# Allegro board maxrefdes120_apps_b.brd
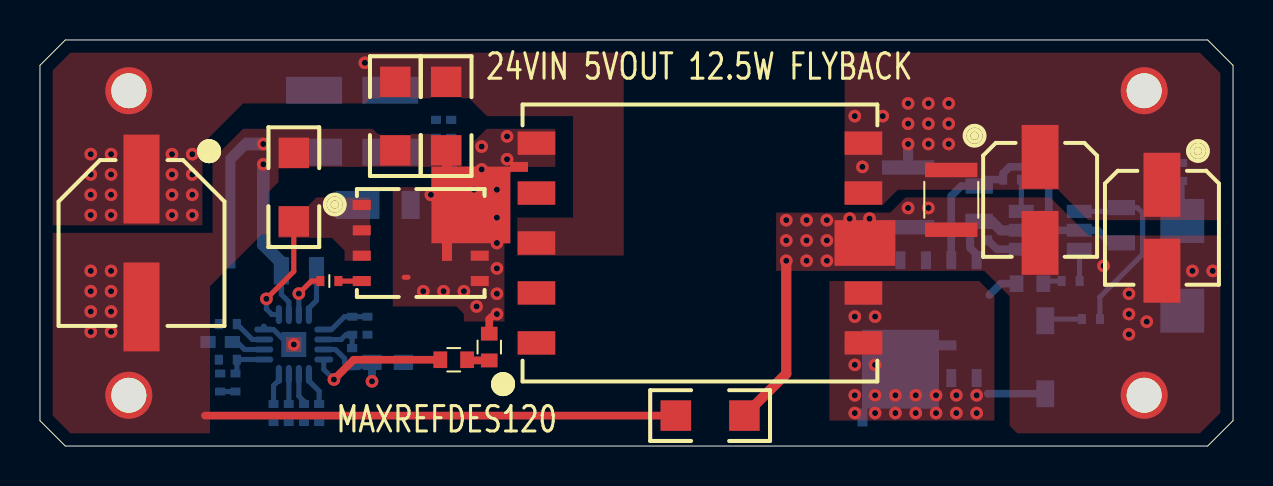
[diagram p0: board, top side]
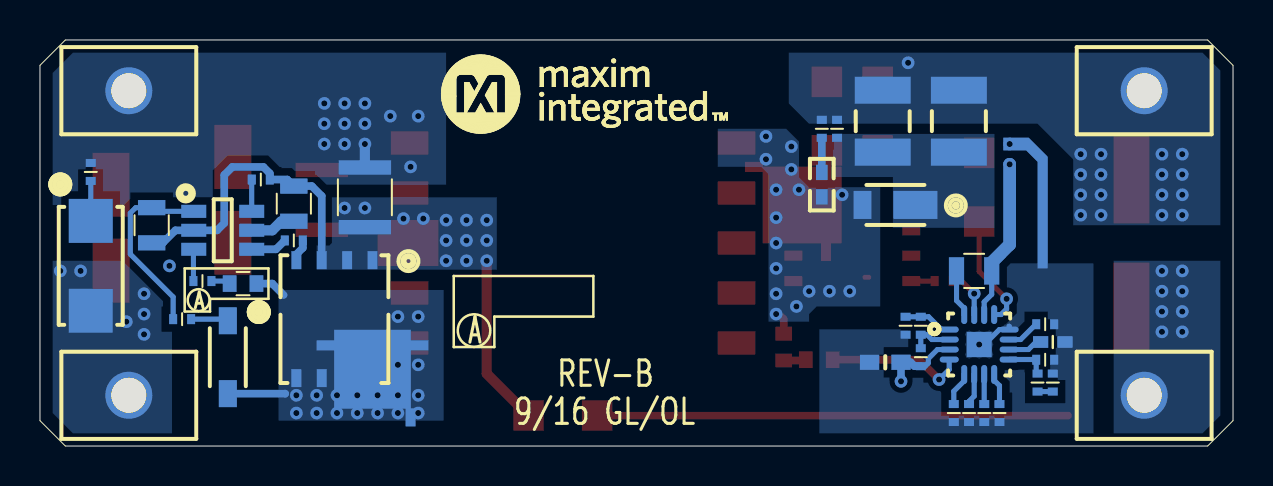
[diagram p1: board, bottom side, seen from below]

Outline 59.69 x 20.32 mm; copper layers: TOP, LAYER2, LAYER3, BOTTOM. Coordinates in mm from the lower left corner of the outline.
Outline path: 0,19.05 1.27,20.32 58.42,20.32 59.69,19.05 59.69,1.27 58.42,0 1.27,0 0,1.27 0,19.05

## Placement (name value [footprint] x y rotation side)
C1  10UF  [1206]  17.78 16.51 270 top
C2  10UF  [1206]  20.32 16.51 270 top
C3  0.047UF  [0402]  19.81 15.88 270 bottom
C4  OPEN  [0402#2]  20.57 13.08 270 bottom
C5  1UF  [0603#2]  17.4 4.19 0 bottom
C6  2.2UF  [0805]  12.95 8.76 0 bottom
C7  4700PF  [0402#2]  9.02 5.21 180 bottom
C8  330PF  [0402]  9.4 4.32 180 bottom
C9  0.033UF  [0402]  9.02 3.17 90 bottom
C10  1000PF  [1206]  33.53 1.52 0 top
C12  2.2UF  [0805]  54.1 11.05 270 bottom
C13  2.2UF  [0805]  46.99 12.13 90 bottom
C15  100UF  [1210]  43.43 12.45 270 bottom
C16  220UF  [CAPAE530X600M]  50.04 12.32 270 top
C17  220UF  [CAPAE530X600M]  56.13 10.92 270 top
C18  47UF  [CAPAE830X690M]  5.08 10.16 270 top
C19  100UF  [1210]  45.59 12.32 270 top
D1  DFLS2100  [POWERI123]  16.89 12.06 0 bottom
D2  1N4148W-7-F  [SOD3718X135M]  50.29 4.45 270 bottom
D3  5.6V  [DIOM5528X230M]  57.15 9.02 270 bottom
EV_KIT_BOX1  SMALL BOX  [EVKIT_PACKAGING]  83.82 40.64 0 top
GND  FWJ-01-01-T-S  [SAMTEC_FWJ-01-01-X-X]  4.45 2.54 90 bottom
GNDO  FWJ-01-01-T-S  [SAMTEC_FWJ-01-01-X-X]  55.24 2.54 90 bottom
N1  FDMS86102LZ  [SON127P615X500X112-8M_POWERPAK_SINGLE]  19.05 10.16 0 top
N2  BSC059N04LSG  [SON127P615X500X112-8M_POWERPAK_SINGLE]  44.96 6.35 270 bottom
NOREF  -  []  59 0.58 0 top
NOREF#2  -  []  12.7 -8.26 0 top
NOREF#3  -  []  30.48 55.88 0 top
NOREF#4  -  []  0 19.05 0 top
NOREF#5  -  []  55.24 2.54 90 top
NOREF#6  -  []  1.27 0 90 top
NOREF#7  -  []  4.45 17.78 0 top
NOREF#8  -  []  37.59 17.53 180 bottom
PTC1  470  [0603]  49.53 8.13 0 bottom
R1  7.5K  [RESC3225X65M]  17.53 16.26 270 bottom
R2  274K  [0402]  15.62 4.45 270 bottom
R3  11.3K  [0402]  15.62 6.02 270 bottom
R4  9.76K  [0402]  16.38 6.02 90 bottom
R5  10K  [0402]  13.97 1.65 270 bottom
R6  OPEN  [0402]  13.21 1.65 270 bottom
R7  49.9K  [0402]  9.4 6.1 180 bottom
R8  75K  [0402]  12.45 1.65 270 bottom
R9  90.9K  [0402]  11.68 1.65 270 bottom
R10  10.5K  [0402]  9.78 3.17 270 bottom
R11  0.012  [1206]  12.7 12.95 90 top
R12  150K  [0603]  20.7 4.32 180 top
R13  OPEN  [0402]  20.57 15.88 270 bottom
R15  10  [0402]  52.58 6.35 180 bottom
R16  1K  [0402]  51.56 8.26 180 bottom
R17  54.9K  [0402]  48.64 13.34 180 bottom
R18  1K  [0603]  22.48 4.95 270 top
R19  10  [0402]  14.48 8.26 0 top
R20  7.5K  [RESC3225X65M]  13.72 16.26 270 bottom
R21  0  [0402]  57.15 13.72 270 bottom
R22  5.1  [0402]  46.99 10.29 180 bottom
T1  750343289  [WURT_750343289]  33.02 10.16 0 top
U1  MAX17690ATE+  [QFN50P300X300X80-17M]  12.7 5.08 180 bottom
U2  MAX17606AZT+  [SOT95P280X110-6M]  50.55 10.79 180 bottom
VIN  FWJ-01-01-T-S  [SAMTEC_FWJ-01-01-X-X]  4.45 17.78 90 bottom
VOUT  FWJ-01-01-T-S  [SAMTEC_FWJ-01-01-X-X]  55.24 17.78 90 bottom
X1  -  [EVKIT_WIRE]  79.38 33.02 0 top

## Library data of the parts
C1 C2 = CAP_NP: alternate symbols: CAPC3216X90L; part number: CAP_NP_1206CAP-1206,10UF,20-0010U-Y6
C3 = CAP_NP: alternate symbols: 0402_NOSILK,CAPC1005X50L; part number: CAP_NP_0402CAP-0402,0.047UF,20-0U047-04C
C4 = EVK_GENERIC_CAPACITORS: alternate symbols: 0402_NOSILK,CAPC1005X50L; part number: EVK_GENERIC_CAPACITORS_0402CAP-0402,N/A
C5 = CAP_NP: alternate symbols: (0603_NOSILK); part number: CAP_NP_0603CAP-0603,1UF,20-0001U-14
C6 C12 C13 = CAP_NP: alternate symbols: CAPC2012X145L,CAPC2012X140M; part number: CAP_NP_0805CAP-0805,2.2UF,20-002U2-04
C7 = CAP_NP: alternate symbols: 0402_NOSILK,CAPC1005X50L; part number: CAP_NP_0402CAP-0402,4700PF,20-4700P-14
C8 = CAP_NP: alternate symbols: 0402_NOSILK,CAPC1005X50L; part number: CAP_NP_0402CAP-0402,330PF,20-0330P-14
C9 = CAP_NP: alternate symbols: 0402_NOSILK,CAPC1005X50L; part number: CAP_NP_0402CAP-0402,0.033UF,20-0U033-04C
C10 = CAP_NP: part number: CAP_NP_1206CAP-1206,1000PF,20-1000P-08B
C15 C19 = CAP_NP: alternate symbols: CAPC3225X270L; part number: CAP_NP_1210CAP-1210,100UF,20-0100U-V5A
C16 C17 = CAP_POL: part number: CAP_POL_CASE_B6-CAPAE530X600M,220UF,20-0220U-CA36
C18 = CAP_POL: part number: CAP_POL_CASEE-CAPAE830X690M,47UF,20-0047U-A49
D1 = DIO_SCHOTTKY: alternate symbols: SODFL3717X100L; part number: DIO_SCHOTTKY_POWERI123-POWERI123,DFLS2100,30-DFLS2100-00
D2 = DIO_SWITCH: part number: DIO_SWITCH_SOD-123-SOD3718X135M,1N4148W-7-F,30-1N4148W7F-00
D3 = DIO_ZENER: part number: DIO_ZENER_DO-214AC-DIOM5528X230M,5.6V,30-SMAZ5V6-00
EV_KIT_BOX1 = EV_KIT_BOX: part number: EV_KIT_BOX_ACCESSORY-N/A,SMALL BOX,EVKIT_PACKAGING
GND GNDO VIN VOUT = HEADER_1P: part number: HEADER_1P_TH-SAMTEC_FWJ-01-01-X-X,FWJ-01-01-T-S,01-FWJ0101TS1P-19
N1 = TRAN_NCH_8P: part number: TRAN_NCH_8P_PG-TSDSON-8-SON127P615X500X112-8M_POWERPAK_SINGLE,FDMS86102LZ,90-FDMS86102LZ-23
N2 = TRAN_NCH_8P: part number: TRAN_NCH_8P_PG-TDSON-8-SON127P615X500X112-8M_POWERPAK_SINGLE,BSC059N04LSG,90-BSC059N04LSG-23
PTC1 = THERMISTOR_SMD: alternate symbols: RESC1608X90L; part number: THERMISTOR_SMD_0603-0603,470,83-0470R-0AD
R1 R20 = RES: alternate symbols: RESC3225X70L; part number: RES_1210RES-RESC3225X65M,7.5K,80-007K5-BA51
R2 = RES: alternate symbols: (0402_NOSILK,RESC1005X50L); part number: RES_0402RES-0402,274K,80-0274K-23
R3 = RES: alternate symbols: 0402_NOSILK,RESC1005X50L; part number: RES_0402RES-0402,11.3K,80-011K3-AA23
R4 = RES: alternate symbols: 0402_NOSILK,RESC1005X50L; part number: RES_0402RES-0402,9.76K,80-09K76-AA23
R5 = RES: alternate symbols: 0402_NOSILK,RESC1005X50L; part number: RES_0402RES-0402,10K,80-0010K-23
R6 R13 = EVK_GENERIC_RESISTORS: alternate symbols: 0402_NOSILK,RESC1005X50L; part number: EVK_GENERIC_RESISTORS_0402RES-0402,N/A
R7 = RES: alternate symbols: (0402_NOSILK,RESC1005X50L); part number: RES_0402RES-0402,49.9K,80-049K9-18
R8 = RES: alternate symbols: (0402_NOSILK,RESC1005X50L); part number: RES_0402RES-0402,75K,80-0075K-23
R9 = RES: alternate symbols: (0402_NOSILK,RESC1005X50L); part number: RES_0402RES-0402,90.9K,80-090K9-23
R10 = RES: alternate symbols: (0402_NOSILK,RESC1005X50L); part number: RES_0402RES-0402,10.5K,80-010K5-18A
R11 = RES: alternate symbols: RESC3116X60L; part number: RES_1206RES-1206,0.012,80-0R012-BA25
R12 = RES: alternate symbols: 0603_NOSILK,RESC1608X90L; part number: RES_0603RES-0603,150K,80-0150K-24
R15 R19 = RES: alternate symbols: (0402_NOSILK,RESC1005X50L); part number: RES_0402RES-0402,10,80-0010R-49
R16 = RES: alternate symbols: 0402_NOSILK,RESC1005X50L,RES0402-NOT_FOR_TEST; part number: RES_0402RES-0402,1K,80-0001K-23
R17 = RES: alternate symbols: (0402_NOSILK,RESC1005X50L); part number: RES_0402RES-0402,54.9K,80-054K9-23
R18 = RES: alternate symbols: 0603_NOSILK,RESC1608X90L; part number: RES_0603RES-0603,1K,80-0001K-24
R21 = RES: alternate symbols: (0402_NOSILK,RESC1005X50L); part number: RES_0402RES-0402,0,80-0000R-26B
R22 = RES: alternate symbols: (0402_NOSILK,RESC1005X50L); part number: RES_0402RES-0402,5.1,80-005R1-U21
T1 = EK_750343289: part number: EK_750343289_SMD-WURT_750343289,750343289,N/A
U1 = MAX17690: part number: MAX17690_TQFN16-EP-QFN50P300X300X80-17M,MAX17690ATE+,10-MAX17690ATE-T
U2 = MAX17606: part number: MAX17606_SOT23-6-SOT95P280X110-6M,MAX17606AZT+,10-MAX17606AZT-Z
X1 = EVKIT_WIRE: part number: EVKIT_WIRE_WIRE-EVKIT_WIRE,N/A,EVKIT_WIRE

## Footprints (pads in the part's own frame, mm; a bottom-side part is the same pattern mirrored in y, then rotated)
0402
  rect 0.4x0.5 smd: 1(-0.45,0) 2(0.45,0)
0402#2
  rect 0.762x0.584 smd: 1(-0.61,0) 2(0.61,0)
0603
  rect 0.69x0.83 smd: 1(-0.67,0) 2(0.67,0)
0603#2
  rect 0.965x0.762 smd: 1(-0.787,0) 2(0.787,0)
0805
  rect 0.76x1.37 smd: 1(-0.88,0) 2(0.88,0)
1206
  rect 1.524x1.524 smd: 1(-1.714,0) 2(1.714,0)
1210
  rect 0.72x2.62 smd: 1(-1.495,0) 2(1.495,0)
CAPAE530X600M
  rect 3.2x1.85 smd: A(-2.15,0) K(2.15,0)
CAPAE830X690M
  rect 4.45x1.8 smd: 1(-3.2,0) 2(3.2,0)
DIOM5528X230M
  rect 2.2x2.2 smd: A(2.25,0) C(-2.25,0)
POWERI123
  rect 0.9x1.4 smd: A(1.65,0)
  rect 2.2x1.4 smd: C(-0.999,0)
QFN50P300X300X80-17M
  oval 0.95x0.3 smd: 1(-1.5,0.75) 2(-1.5,0.25) 3(-1.5,-0.25) 4(-1.5,-0.75) 9(1.5,-0.75) 10(1.5,-0.25) 11(1.5,0.25) 12(1.5,0.75)
  oval 0.3x0.95 smd: 5(-0.75,-1.5) 6(-0.25,-1.5) 7(0.25,-1.5) 8(0.75,-1.5) 13(0.75,1.5) 14(0.25,1.5) 15(-0.25,1.5) 16(-0.75,1.5)
  rect 1.25x1.25 smd: 17(0,0)
RESC3225X65M
  rect 1.35x2.8 smd: 1(-1.55,0) 2(1.55,0)
SAMTEC_FWJ-01-01-X-X
  round 2.35 hole 1.75: 1(0,0)
SOD3718X135M
  rect 1.35x0.9 smd: A(1.825,0) C(-1.825,0)
SON127P615X500X112-8M_POWERPAK_SINGLE
  rect 0.9x0.5 smd: 1(-2.95,1.905) 2(-2.95,0.635) 3(-2.95,-0.635) 4(-2.95,-1.905) 5(2.95,-1.905) 6(2.95,-0.635) 7(2.95,0.635)
  custom 1.209x1.209 smd: 8(2.95,1.905)
SOT95P280X110-6M
  rect 1.25x0.65 smd: 1(-1.45,0.95) 2(-1.45,0) 3(-1.45,-0.95) 4(1.45,-0.95) 5(1.45,0) 6(1.45,0.95)
WURT_750343289
  rect 1.88x1.17 smd: 1(-8.18,-5) 2(-8.18,-2.5) 3(-8.18,0) 4(-8.18,2.5) 5(-8.18,5) 6(8.18,5) 7(8.18,2.5) 8(8.18,0) 9(8.18,-2.5) 10(8.18,-5)

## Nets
GNDO: C10.2 C12.2 C13.2 C15.2 C16.K(B) C17.K(B) C19.2 D3.A GNDO.1 N2.1(S1) N2.2(S2) N2.3(S3) R17.2 U2.2(GND)
PGND: C1.2 C2.2 C6.1 C10.1 C18.2(B) GND.1 R11.2 U1.14(PGND)
SGND: C5.2 C7.2 C8.2 C9.2 R4.1 R5.2 R6.2 R7.2 R8.2 R9.2 U1.12(SGND) U1.17(EP)
VIN: C1.1 C2.1 C3.1 C5.1 C18.1(A) R1.1 R2.2 R13.1 R20.1 T1.3 U1.3(VIN) VIN.1
LX: C4.2 D1.A N1.5(D1) N1.6(D2) N1.7(D3) N1.8(D4) R18.1 T1.5
UNNAMED_4_CAPNP_I112_2: C3.2 D1.C(K) R1.2 R20.2
UNNAMED_4_CAPNP_I179_2: C6.2 U1.16(INTVCC)
UNNAMED_4_CAPNP_I180_1: C13.1 U2.5(VDRV)
UNNAMED_4_CAPNP_I182_1: C8.1 R10.1 U1.9(COMP)
UNNAMED_4_CAPNP_I183_1: C9.1 R10.2
UNNAMED_4_CAPNP_I184_1: C12.1 R15.1 U2.1(VIN)
UNNAMED_4_CAPNP_I216_1: C7.1 U1.10(SS)
UNNAMED_4_DIOSWITCH_I187_A: D2.A N2.5(D1) N2.6(D2) N2.7(D3) N2.8(D4) PTC1.1 T1.9 T1.10
UNNAMED_4_DIOSWITCH_I187_K: D2.C(K) R15.2
UNNAMED_4_DIOZENER_I178_K: D3.C(K) R21.2
UNNAMED_4_EVKGENERICCAPACITORS_I151_1: C4.1 R13.2
UNNAMED_4_EVKGENERICRESISTORS_I167_1: R6.1 U1.6(TC)
UNNAMED_4_MAX17606_I176_DRN: R16.1 U2.3(DRN)
UNNAMED_4_MAX17606_I176_GATE: R22.1 U2.4(GATE)
UNNAMED_4_MAX17606_I176_TOFF: R17.1 U2.6(TOFF)
UNNAMED_4_MAX17690_I155_CS: N1.1(S1) N1.2(S2) N1.3(S3) R11.1 U1.13(CS)
UNNAMED_4_MAX17690_I155_EN: R2.1 R3.2 U1.2(EN/UVLO)
UNNAMED_4_MAX17690_I155_FB: R12.2 U1.4(FB)
UNNAMED_4_MAX17690_I155_NDRV: R19.1 U1.15(NDRV)
UNNAMED_4_MAX17690_I155_OVI: R3.1 R4.2 U1.1(OVI)
UNNAMED_4_MAX17690_I155_RIN: R9.1 U1.8(RIN)
UNNAMED_4_MAX17690_I155_RT: R7.1 U1.11(RT)
UNNAMED_4_MAX17690_I155_SET: R5.1 U1.5(SET)
UNNAMED_4_MAX17690_I155_VCM: R8.1 U1.7(VCM)
UNNAMED_4_RESSMD_I171_1: R12.1 R18.2
UNNAMED_4_RESSMD_I173_2: PTC1.2 R16.2
UNNAMED_4_RESSMD_I175_2: N1.4(G) R19.2
UNNAMED_4_RESSMD_I224_2: N2.4(G) R22.2
VOUT: C15.1 C16.A C17.A C19.1 R21.1 T1.6 T1.7 VOUT.1

Pads without a net: T1 1 2 4 8

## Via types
v1: diameter 0.635, hole 0.305, TOP to BOTTOM, 98 vias

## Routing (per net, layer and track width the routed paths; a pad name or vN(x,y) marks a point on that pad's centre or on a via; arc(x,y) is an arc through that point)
GNDO: length 23.6
  TOP w0.508: v1(37.34,9.27) 37.34,3.62 C10.2
  BOTTOM w0.381: 45.59,9.81 45.59,12.51 46.09,13.01 C13.2 47.32,13.34 R17.2 48.19,13.64 48.51,13.97 50.07,13.97 50.47,13.56 50.47,11.15 50.83,10.79 U2.2 52.91,10.79 53.54,10.17 C12.2
  vias: v1(37.34,11.3) v1(37.34,10.29) v1(38.35,11.3) v1(38.35,10.29) v1(38.35,9.27) v1(39.37,11.3) v1(39.37,10.29) v1(39.37,9.27) v1(40.51,11.38) v1(41.5,11.38) v1(43.43,11.91) v1(44.45,11.91) v1(53.21,9.02) v1(54.48,7.62) v1(54.48,6.6) v1(54.48,5.59) v1(55.37,6.22) v1(57.66,8.76) v1(58.67,8.76)
PGND: length 31.6
  TOP w0.381: C10.1 8.26,1.52
  BOTTOM w0.254: C6.1 12.07,7.59 12.45,7.21 U1.14
  BOTTOM w0.635: v1(11.18,14.1) 11.18,10.08 12.07,9.18 C6.1
  vias: v1(2.54,8.76) v1(2.54,7.75) v1(2.54,6.73) v1(2.54,5.71) v1(3.56,8.76) v1(3.56,7.75) v1(3.56,6.73) v1(3.56,5.71) v1(11.18,15.11)
SGND: length 2
  BOTTOM w0.254: 11.2,5.99 11.2,5.99 U1.12 11.69,5.83 12.44,5.08 v1(12.7,5.08)
VIN: length 20
  LAYER3 w1.016: v1(16.26,19.18) 16.26,3.59 v1(16.61,3.24)
  BOTTOM w0.254: R2.2 15.4,3.99 15.24,4.15 15.24,4.37 14.79,4.83 U1.3
  BOTTOM w0.381: v1(16.61,3.24) C5.1 16.13,4.19 15.93,3.99 R2.2
  vias: v1(2.54,14.61) v1(2.54,13.59) v1(2.54,12.57) v1(2.54,11.56) v1(3.56,14.61) v1(3.56,13.59) v1(3.56,12.57) v1(3.56,11.56) v1(6.6,14.61) v1(6.6,13.59) v1(6.6,12.57) v1(6.6,11.56) v1(7.62,14.61) v1(7.62,13.59) v1(7.62,12.57) v1(7.62,11.56)
LX: length 1.1
  TOP w0.254: 18.22,8.45 18.41,8.45
  TOP w0.381: 22.61,6.48 22.48,6.35 R18.1
  vias: v1(19.18,7.75) v1(19.56,12.57) v1(20.19,7.75) v1(21.21,7.75) v1(21.72,12.83) v1(21.84,6.99) v1(22.1,14.99) v1(22.1,13.84) v1(22.86,12.83) v1(22.86,11.43) v1(22.86,10.16) v1(22.86,8.89) v1(22.86,7.62) v1(22.86,6.6) v1(23.37,15.49) v1(23.37,14.35)
UNNAMED_4_CAPNP_I179_2: length 2.3
  BOTTOM w0.254: C6.2 13.83,7.28 13.45,6.9 U1.16
UNNAMED_4_CAPNP_I180_1: length 2.3
  BOTTOM w0.508: C13.1 47,11.24 47.62,11.24 48.07,10.79 U2.5
UNNAMED_4_CAPNP_I182_1: length 2.1
  BOTTOM w0.254: R10.1 9.85,3.69 C8.1 9.86,4.33 U1.9
UNNAMED_4_CAPNP_I183_1: length 0.8
  BOTTOM w0.254: R10.2 C9.1
UNNAMED_4_CAPNP_I184_1: length 9.6
  BOTTOM w0.254: R15.1 53.03,7.46 55.17,9.6 55.17,11.66 54.9,11.93 C12.1 53.92,11.75 U2.1
UNNAMED_4_CAPNP_I216_1: length 1.7
  BOTTOM w0.254: U1.10 10.24,4.83 9.86,5.21 C7.1
UNNAMED_4_DIOSWITCH_I187_A: length 4.5
  BOTTOM w0.381: 47.42,2.62 47.43,2.62 D2.A ; PTC1.1 48.07,8.13 47.5,7.56
  vias: v1(40.77,6.48) v1(40.77,4.06) v1(40.77,2.54) v1(40.77,1.65) v1(41.78,6.48) v1(41.78,4.06) v1(41.78,2.54) v1(41.78,1.65) v1(42.8,2.54) v1(42.8,1.65) v1(43.81,2.54) v1(43.81,1.65) v1(44.83,2.54) v1(44.83,1.65) v1(45.85,2.54) v1(45.85,1.65) v1(46.86,2.54) v1(46.86,1.65)
UNNAMED_4_DIOSWITCH_I187_K: length 1.9
  BOTTOM w0.254: R15.2 50.37,6.35 D2.C
UNNAMED_4_DIOZENER_I178_K: length 2
  BOTTOM w0.254: R21.2 D3.C
UNNAMED_4_EVKGENERICCAPACITORS_I151_1: length 1.7
  BOTTOM w0.381: R13.2 C4.1
UNNAMED_4_EVKGENERICRESISTORS_I167_1: length 1.6
  BOTTOM w0.254: R6.1 13.21,2.24 12.95,2.5 U1.6
UNNAMED_4_MAX17606_I176_DRN: length 1.6
  BOTTOM w0.254: R16.1 52.01,9.83 U2.3
UNNAMED_4_MAX17606_I176_GATE: length 1.8
  BOTTOM w0.381: R22.1 47.88,9.84 U2.4
UNNAMED_4_MAX17606_I176_TOFF: length 1.6
  BOTTOM w0.254: R17.1 49.1,13.33 U2.6
UNNAMED_4_MAX17690_I155_CS: length 5.7
  TOP w0.254: v1(11.33,7.37) 12.7,8.74 R11.1
  BOTTOM w0.254: U1.13 11.61,6.58 11.33,6.86 v1(11.33,7.37)
UNNAMED_4_MAX17690_I155_EN: length 2.2
  BOTTOM w0.254: R2.1 R3.2 15.31,5.57 15.07,5.33 U1.2
UNNAMED_4_MAX17690_I155_FB: length 6.9
  TOP w0.381: v1(14.71,3.33) 15.7,4.32 R12.2
  BOTTOM w0.254: v1(14.71,3.33) 14.2,3.83 U1.4
UNNAMED_4_MAX17690_I155_NDRV: length 2.4
  TOP w0.254: R19.1 13.58,8.26 v1(12.95,7.63)
  BOTTOM w0.254: U1.15 v1(12.95,7.63)
UNNAMED_4_MAX17690_I155_OVI: length 2.4
  BOTTOM w0.254: U1.1 14.59,5.83 15.23,6.47 R3.1 R4.2
UNNAMED_4_MAX17690_I155_RIN: length 1.6
  BOTTOM w0.254: U1.8 11.95,3.29 11.68,3.02 R9.1
UNNAMED_4_MAX17690_I155_RT: length 1.7
  BOTTOM w0.254: U1.11 10.63,5.33 9.86,6.1 R7.1
UNNAMED_4_MAX17690_I155_SET: length 1.7
  BOTTOM w0.254: R5.1 13.97,2.74 13.45,3.26 U1.5
UNNAMED_4_MAX17690_I155_VCM: length 1.5
  BOTTOM w0.254: U1.7 12.45,2.1 R8.1
UNNAMED_4_RESSMD_I171_1: length 1.1
  TOP w0.381: R18.2 21.41,4.28 R12.1
UNNAMED_4_RESSMD_I173_2: length 1
  BOTTOM w0.254: R16.2 50.33,8.26 PTC1.2
UNNAMED_4_RESSMD_I175_2: length 1.2
  TOP w0.254: N1.4 R19.2
UNNAMED_4_RESSMD_I224_2: length 1.1
  BOTTOM w0.381: N2.4 46.86,9.59 46.54,9.91 R22.2
VOUT: length 1.2
  BOTTOM w0.508: C15.1 v1(43.43,15.11)
  vias: v1(40.77,16.51) v1(41.15,13.97) v1(42.16,16.51) v1(43.43,17.14) v1(43.43,16.13) v1(44.45,17.14) v1(44.45,16.13) v1(44.45,15.11) v1(45.47,17.14) v1(45.47,16.13) v1(45.47,15.11)

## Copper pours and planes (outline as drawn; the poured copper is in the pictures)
GNDO on TOP (solid shape): 42.8,9.02 39.75,9.02 39.75,11.3 42.8,11.3
GNDO on TOP: 48.89,0.64 48.51,1.02 48.51,7.49 47.24,8.76 36.83,8.76 36.83,11.68 42.55,11.68 43.31,12.45 50.55,12.45 52.45,10.54 59.05,10.54 59.05,1.65 58.04,0.64
GNDO on BOTTOM: 53.09,0.64 53.09,6.86 55.5,9.27 59.05,9.27 59.05,1.65 58.04,0.64
GNDO on BOTTOM: 39.43,8.83 45.85,8.83 45.85,10.03 45.21,10.03 45.09,10.16 45.09,12.45 36.83,12.45 36.83,8.83
GNDO on LAYER2: 48.89,0.64 48.51,1.02 48.51,7.49 47.12,8.89 36.83,8.89 36.83,11.68 42.55,11.68 43.31,12.45 50.55,12.45 52.45,10.54 59.05,10.54 59.05,1.65 58.04,0.64
GNDO on LAYER3: 48.89,0.64 48.51,1.02 48.51,7.49 47.12,8.89 36.83,8.89 36.83,11.68 42.55,11.68 43.31,12.45 50.55,12.45 52.45,10.54 59.05,10.54 59.05,1.65 58.04,0.64
PGND on TOP: 8.51,0.64 8.51,8 11.1,10.59 11.43,10.59 11.43,12.7 12.7,13.97 21.08,13.97 21.08,15.62 16.89,15.62 16.64,15.88 10.16,15.88 8.64,14.35 8.64,10.67 0.64,10.67 0.64,1.52 1.52,0.64
PGND on BOTTOM: 0.64,9.27 0.64,1.52 1.52,0.64 5.97,0.64 5.97,9.27
PGND on LAYER3: 0.64,9.53 8.26,9.53 8.26,0.64 1.52,0.64 0.64,1.52
SGND on BOTTOM (solid shape): 11.49,14.8 10.35,14.8 9.78,14.22 9.78,8.89 9.27,8.89 9.27,14.48 10.22,15.43 11.49,15.43
SGND on BOTTOM: 20.7,5.84 15.49,5.84 15.49,3.17 13.97,3.17 13.97,6.73 13.84,6.73 11.43,9.14 6.99,9.14 6.99,0.64 20.7,0.64
VIN on TOP: 0.64,11.05 0.64,18.8 1.52,19.68 29.21,19.68 29.21,9.53 23.88,9.53 23.88,11.43 26.67,11.43 26.67,16.51 22.35,16.51 21.46,17.4 16.51,17.4 16.26,17.14 10.16,17.14 8.13,15.11 8.13,11.05
VIN on BOTTOM: 8,11.05 0.64,11.05 0.64,18.8 1.52,19.68 22.23,19.68 22.23,17.14 21.21,16.13 9.78,16.13 8,14.35
VIN on LAYER3: 0.64,10.79 0.64,18.8 1.52,19.68 8.89,19.68 8.89,11.43 8.89,10.8 8.26,10.79
LX on TOP, BOTTOM, LAYER2, LAYER3: 25.78,13.97 25.78,15.88 22.35,15.88 21.72,15.24 21.72,13.46 21.21,12.95 17.65,12.95 17.65,6.99 20.83,6.99 21.21,6.6 21.21,6.22 23.24,6.22 23.24,13.59 23.62,13.97
UNNAMED_4_CAPNP_I112_2 on BOTTOM: 20.07,15.62 20.07,13.46 17.02,13.46 17.02,10.92 11.94,10.92 11.94,15.62
UNNAMED_4_DIOSWITCH_I187_A on TOP: 47.75,1.27 39.5,1.27 39.5,8.26 46.99,8.26 47.75,7.49
UNNAMED_4_DIOSWITCH_I187_A on BOTTOM: 47.75,1.27 39.5,1.27 39.5,7.81 39.5,7.81 47.69,7.81 47.75,7.81
UNNAMED_4_DIOSWITCH_I187_A on LAYER2, LAYER3: 46.99,8.26 47.75,7.49 47.75,1.27 39.5,1.27 39.5,8.26
UNNAMED_4_MAX17690_I155_CS on TOP: 16.51,12.45 13.84,12.45 13.34,11.94 11.94,11.94 11.94,10.41 14.61,10.41 15.24,9.78 15.24,9.27 16.51,9.27
VOUT on TOP: 59.05,18.67 58.04,19.68 40.26,19.68 40.26,12.06 42.16,12.06 42.93,12.83 50.93,12.83 52.45,11.3 59.05,11.3
VOUT on BOTTOM: 49.66,12.06 48.64,13.08 39.37,13.08 39.37,19.68 58.04,19.68 59.05,18.67 59.05,12.06
VOUT on LAYER2: 59.05,18.67 58.04,19.68 39.37,19.68 39.37,12.83 50.93,12.83 52.45,11.3 59.05,11.3
VOUT on LAYER3: 59.05,18.67 58.04,19.68 39.37,19.68 39.37,12.83 50.93,12.83 52.45,11.3 59.05,11.3

Small or netless copper shapes (teardrops, artwork), in the pictures only: 1 on TOP

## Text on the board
Ref Des/Silkscreen Bottom: A | REV-B | 9/16 GL/OL
Ref Des/Silkscreen Top: MAXREFDES120 | 24VIN 5VOUT 12.5W FLYBACK
DIMENSION: NOTES: | FINISH: | TESTING: | MISCELLANEOUS: | TOOLING: | 16.  VENDOR LOGO & DATE CODE REQUIRED IN INK ON BOTTOM SIDE ONLY. DATE CODE FORMAT MUST BE YYWW ONLY | 17.  FINAL ELECTRICAL TEST TO BE PERFORMED USING PROVIDED IPC-D-356A NETLIST OR ODB++ FORMAT FILE. | 18.  A TIME DOMAIN REFLECTOMETER REPORT FOR EACH IMPEDANCE CONTROLLED LAYER AND A CERTIFICATE | 15.  CHECK ALL THAT APPLY | 14.  CHECK ALL THAT APPLY | 19. IF PRESENT, ALL BLIND/BURIED VIAS WITH AN ASPECT RATIO <1:1 TO BE PLATED SHUT WITH COPPER WHEN | 20.  FOR ALL DRILL INFORMATION REFER TO DRILL CHART. | 21.  FINISHED SURFACE CONTACTS AND FILLED VIAS TO BE FREE OF ANY PITS. SCRATCHES PROBE MARKS | 23.  PEMNUT | 13.  DRILL SIZES ARE FINISHED HOLE SIZES. ALL HOLES SHALL BE LOCATED WITHIN .005 DTP. | 22.  THIEVING: | 9.  ALL TRACES FILLETED OPTION TO ENHANCE RELIABILITY AT PAD JUNCTIONS | 10.  LAYER TO LAYER REGISTRATIONS SHALL BE WITHIN .003 INCHES. | MATERIAL: | 11.  PLATING SPECIFICATION: | 12.  CHECK ALL THAT APPLY | 8.  IF STATED IN THE LAMINATION DIAGRAM, THE DIELECTRIC THICKNESS OF ANY | 1.  DIMENSIONS ARE IN INCHES (EXCEPT WHERE NOTED). | 3.  THE PCB SHALL BE FABRICATED TO IPC-6012, TYPE X, CLASS 2. | 4.  BOARD MATERIAL & CONSTRUCTION SHALL MEET THE REQUIREMENTS OF UL796 | 5.  OVERALL BOARD THICKNESS REFER TO LAMINATION DIAGRAM. TOLERANCE APPLIES | 6.  BOW & TWIST NOT TO EXCEED 0.0075 IN. (0.75%) PER LINEAR INCH. | 7.  PHOTO ETCH CIRCUITRY PER ENCLOSED GERBER RS274X OR ODB++ FORMAT FILE. | 2.  BOARD MATERIAL: | ( )  FINISH CONDUCTOR SURFACES: IMMERSION GOLD, 2-5 MICRO INCHES OVER | (X)  STARTING COPPER WEIGHT FOR OUTER LAYERS TO BE (1 OZ), THE FINISH COPPER WEIGHT IS (1 OZ). | ( )  STARTING COPPER WEIGHT FOR OUTER LAYERS TO BE (1 OZ), THE FINISH COPPER WEIGHT IS (2 OZ). | ( )  STARTING COPPER WEIGHT FOR OUTER LAYERS TO BE (2 OZ), THE FINISH COPPER WEIGHT IS (2 OZ)MINIMUM. | ( )  OTHER ________________________ | ( )  FINISH CONDUCTOR SURFACES: IMMERSION GOLD, 3-8 MICRO INCHES OVER | ( )  FINGERS TO BE GOLD PLATED. | (X)  LEAD FREE AND RoHS COMPLIANT PLATING. | (X)  GREEN SOLDERMASK OVER BARE COPPER/BARE GOLD (BOTH SIDES) WITH LIQUID PHOTO IMAGEABLE INK (LPI) | ( )  GREEN TAIYO PSR-4000 | ( )  ELECTRODEPOSITED HARD GOLD PLATE, TYPE 1 (99.7% MIN GOLD), GRADE C | (X)  APPLY SILKSCREEN USING A NON-CONDUCTIVE, WHITE EPOXY | THE STARTING WEIGHT CAN BE (0.5 OZ) AS LONG AS THE FINISH COPPER WEIGHT IS (2 OZ). | THE STARTING WEIGHT CAN BE (<2 OZ) AS LONG AS THE FINISH COPPER WEIGHT IS (2 OZ). | MINIMUM BARREL PLATING OF .001 IN. PLATED HOLES SHALL NOT BE ROUGH OR IRREGULAR | SO AS TO HINDER PROPER SOLDER WICKING. | USED AS VIA-IN PAD OR AS A STACKED VIA. BLIND/BURIED VIAS WITH AN ASPECT RATIO >1:1 TO BE FILLED | WITH NON-CONDUCTIVE EPOXY. UNLESS OTHERWISE SPECIFIED. | ( )  NON-CONDUCTIVE EPOXY. FILL AND CAP ALL 0.XXXX INCH DRILLED VIAS. | ( )  SILVER. FILL AND CAP ALL 0.XXXX INCH DRILLED VIAS. | (REQUIRED UNLESS OTHERWISE SPECIFIED IN QUOTE) | THE PCB SHALL HAVE A VERIFICATION STAMP. | OF COMPLIANCE SHALL BE PROVIDED BY VENDOR AT TIME OF SHIPMENT. | OR OTHER DEFORMITIES THAT COULD EFFECT THE APPERANCE AND PERFORMACE OF THE CONTACT | SURFACE. CONTACTS ARE TO BE AS FLAT AS POSSIBLE. NOT TO EXCEED +/- 0.001" OF FLATNESS. | ( )  SUPPLIER MAY ADD THIEVING TO COMPENSATE FOR LOW COPPER DENSITY AREAS ON THIS DESIGN. | WHERE SPACING PERMITS. | LEGEND TO LEGEND +/- 0.007 INCHES | (X)  SUPPLIER MAY NOT ADD THIEVING TO COMPENSATE FOR LOW COPPER DENSITY AREAS ON THIS DESIGN. | ( )  PEMNUTS TO BE INSTALLED BY SUPPLIER | ( )  PEMNUTS NOT TO BE INSTALLED BY SUPPLIER | (X)  NOT APPLICABLE | CONTROLLED IMPEDANCE LAYER IS FOR REFERENCE ONLY. FINAL ACCEPTANCE | SHALL BE DETERMINED BY THESE LAYERS HAVING A CHARACTERISTIC | IMPEDANCE OF +/-10% OHMS AS STATED IN THE LAMINATION DIAGRAM. THE | VENDOR CAN MAKE ADJUSTMENTS AS LONG AS THE STATED IMPEDANCE AND | OVERALL BOARD THICKNESS IS MAINTAINED. ANY ADJUSTMENT MADE TO TRACE | WIDTH OR SPACING MUST HAVE PRIOR WRITTEN APPROVAL FROM MAXIM. | ( )  FILLETED | (X)  NOT FILLETED | (X)  ISOLA 370HR OR EQUIVALENT | ( )  NELCO-4000-13 | ( )  MEGTRON 6 | ( )  ROGERS 4350B | ( )  ROGERS 4003C | ( )  ISOLA-FR408HR OR EQUIVALENT | WORKMANSHIP SHALL CONFORM TO IPC-A-600, CLASS 2, CURRENT REVISIONS. | WITH FLAMMABILITY RATING OF 94V-O. | AFTER ALL LAMINATION AND PLATING PROCESSES. IT IS TO BE MEASURED FROM | TOP PCB METAL TO BOTTOM PCB METAL UNLESS OTHERWISE SPECIFIED. | BOW & TWIST SHOULD BE MEASURED PER IPC-TM-650, METHOD 2.4.22. | DRILL LOCATION AND SIZE CONTROLLED BY EXCELLON CNC DRILL FILE. | FOR OUTER LAYERS WHERE SPACING PREVENTS THE USE OF (1 OZ) AS A STARTING WEIGHT, | FOR OUTER LAYERS WHERE SPACING PREVENTS THE USE OF (2 OZ) AS A STARTING WEIGHT, | UNLESS OTHERWISE SPECIFIED | FOR OUTER LAYERS WHERE SPACING PREVENTS THE USE OF (1 OZ) AS A STARTING WEIGHT | THE STARTING WEIGHT CAN BE (0.5 OZ) AS LONG AS THE FINISH COPPER WEIGHT IS (1 OZ) | (KNOOP HARDNESS 130-200), CLASS 1 (50-100 MICRO INCHES THICK) IN ACCORDANCE WITH MIL-G-45204C. | GENERAL SURFACING REQUIREMENTS MUST MEET ANSI/IPC-A-600(CURRENT REV) SECTION 4.0, | CLASS 3 (50-100 MICROINCHES THICK) OVER ELECTRODEPOSITED NICKEL PLATE | IN ACCORDANCE WITH ANSI/IPC-A-600D, SECTION 4.0, CLASS 3 (200-600 MICROINCHES THICK). | 100 MICRO INCHES MINIMUM OF ELECTROLESS NICKEL. | 118-236 MICRO INCHES MINIMUM OF ELECTROLESS NICKEL. | PER ARTWORK. | BASED INK PER ARTWORK. | (USE CHECKED ITEMS FOR MATERIAL) | (USE CHECKED ITEMS FOR PLATING) | (USE CHECKED ITEMS FOR TOOLING) | UNLESS OTHERWISE SPECIFIED: | TOLERANCES UNLESS OTHERWISE SPECIFIED | FRACTIONS | SEE NOTES | .XXX +/- .005 | .XX +/- .01 | DECIMALS | +/- | ANGLES | THE INFORMATION CONTAINED IN THIS DOCUMENT | IS PROPRIETARY TO MAXIM. THE INFORMATION IN | THIS DOCUMENT IS NOT TO BE SHOWN, REPRODUCED, | OR DISCLOSED TO ANYONE OUTSIDE OF MAXIM | WITHOUT PRIOR WRITTEN PERMISSION FROM MAXIM. | NOT TO SCALE | x4 corners | DRAWN BY: | CHECKED BY: | APPR. BY: | DATE: | 9/20/16 | HARDWARE NUMBER: | 24VIN 5VOUT 12.5W FLYBACK CONVERTER | TEMPLATE REV B | SHEET 1 OF 1 | REV | HARDWARE NAME: | MAXREFDES120_APPS | B | DESCRIPTION | REVISIONS | APPROVED | DATE
User.16: FIGURE | SIZE | 12.0 | 68.898 | DRILL CHART: TOP to BOTTOM | ALL UNITS ARE IN MILS | TOLERANCE | +3.0/-10.0 | +3.0/-3.0 | PLATED | QTY | 98 | 4
User.22: 1"
